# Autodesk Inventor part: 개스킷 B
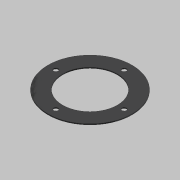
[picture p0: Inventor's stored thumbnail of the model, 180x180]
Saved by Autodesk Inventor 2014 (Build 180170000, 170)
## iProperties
Created: 2020-08
Part Number: 개스킷 B
Material: 고무
Document SubType Name: Modeling
Designer: mduedu
Density: 0.93 g/cm^3
Appearance: 고무 - 검은색 - 버전 1.1
Mass: 2.64047 g
Surface Area: 61.4967 cm^2
Volume: 2.83921 cm^3
Author: mduedu
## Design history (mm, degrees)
sketch "스케치1"
  geometry: C1 r 40 at (0, 0); C2 r 26 at (0, 0); 1 further point
  constraints: 2 centre point, 2 coincident
  dimensions: "d0" = 80 diameter of C1; "d1" = 52 diameter of C2
extrude "돌출1" new body sketch "스케치1" distance "d2" = 1; taper "d3" = 0 deg
sketch "스케치2" dims "d4" = 65
  geometry: 3 further points
  constraints: 2 vertical alignment, 1 coincident, 2 other
hole "구멍1" sketch "스케치2" at (0, 32.5) diameter "d5" = 4.5; stored, may be unused: countersink angle "d9" = 90 deg, drill point angle "d11" = 118 deg; dims "d6" = 6, "d7" = 4, "d8" = 2, "d10" = 8
node "솔리드1"
pattern_circular "원형 패턴1" dims angle "d13" = 360 deg
